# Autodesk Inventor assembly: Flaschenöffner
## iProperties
Created: 2007-01
Part Number: Flaschenöffner
Document SubType Name: Assembly
Designer: Kumpf
Manufacturer: Standard
Standards Organization: Custom
Author: Kumpf
